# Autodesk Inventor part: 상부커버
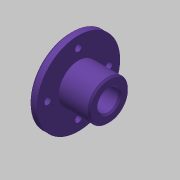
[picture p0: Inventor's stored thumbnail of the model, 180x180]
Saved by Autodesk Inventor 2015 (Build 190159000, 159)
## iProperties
Created: 2015-09
Part Number: 상부커버
Material: 알루미늄 6061
Document SubType Name: Modeling
Designer: mduedu
Density: 1 g/cm^3
Appearance: 보라색
Author: mduedu
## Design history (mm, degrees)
sketch "스케치1"
  geometry: L1 (-12.5, 0)-(12.5, 0); L2 (-12.5, 0)-(-12.5, 27); L3 (-12.5, 27)-(-7.5, 27); L4 (-7.5, 27)-(-7.5, 13); L5 (-7.5, 13)-(12.5, 13); L6 (12.5, 13)-(12.5, 0); 2 further points
  constraints: 12 end point, 2 parallel, 2 perpendicular, 1 coincident, 1 horizontal, 1 midpoint, 1 vertical
  dimensions: "d0" = 25 distance of L1.start L1.end; "d2" = 5 distance of L2.end L3.end; "d3" = 26 diameter of L5 L1; "d4" = 54 diameter of L3 L1
revolve "회전1" sketch "스케치1" stored, may be unused: angle "d5" = 90 deg
hole "구멍1" diameter "d8" = 14; stored, may be unused: countersink angle "d12" = 90 deg, drill point angle "d14" = 118 deg; dims "d6" = 10, "d7" = 10, "d9" = 6, "d10" = 4, "d11" = 2, "d13" = 8
chamfer "모따기1" distance "d15" = 1; stored, may be unused: second distance "d16" = 2, angle "d17" = 45 deg
chamfer "모따기2" distance "d18" = 1; stored, may be unused: second distance "d19" = 2, angle "d20" = 45 deg
sketch "스케치2" dims "d21" = 40
  geometry: 6 further points
  constraints: 2 vertical alignment, 1 coincident, 7 other
  dimensions: "d25" = 360 deg dimension on point (0, 0) point (0, 20) (derived)
sketch "스케치3"
  geometry: 4 further points
hole "구멍2" sketch "스케치3" at (0, 20), (-20, 0), (20, 0), (0, -20) diameter "d27" = 4.5; stored, may be unused: countersink angle "d31" = 90 deg, drill point angle "d33" = 0 deg; dims "d28" = 6, "d29" = 4, "d30" = 2, "d32" = 8
chamfer "모따기3" distance "d34" = 1; stored, may be unused: second distance "d35" = 2, angle "d36" = 45 deg
node "솔리드1"
